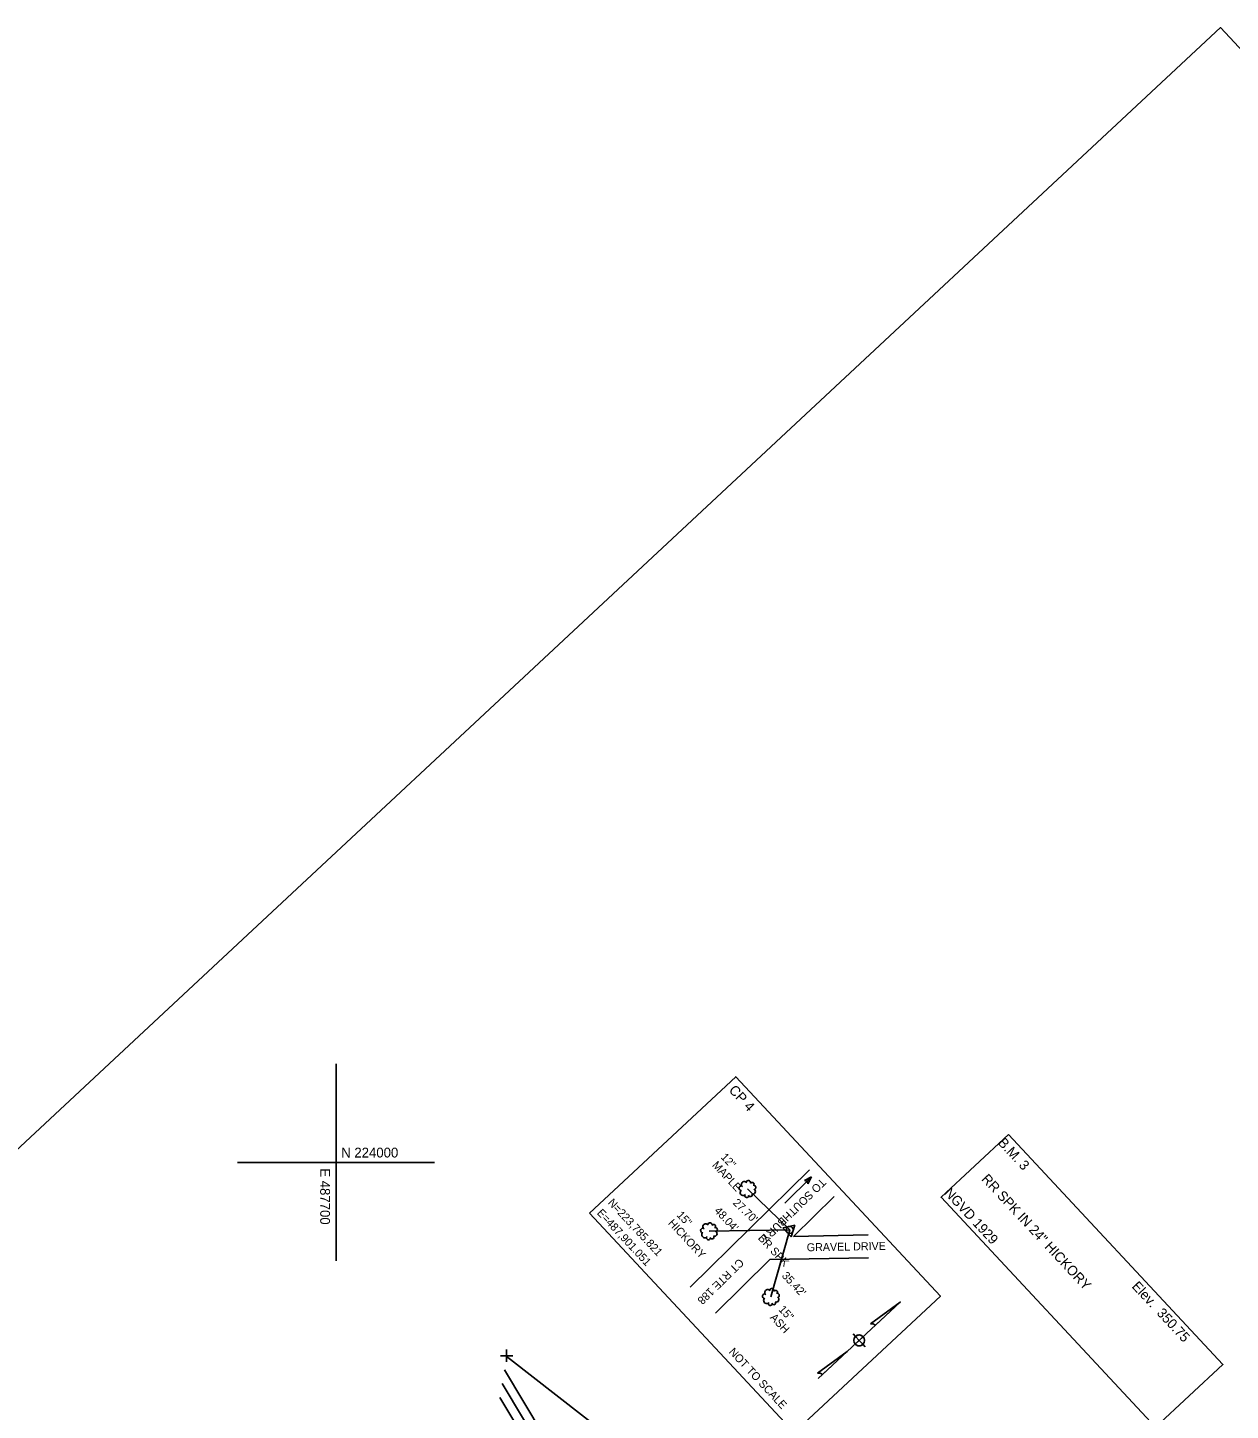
# Model space of a CAD drawing. Extents: x 487096 to 489566, y 221939 to 224454.
# Drawn here: x 487577 to 488058, y 223901 to 224454 of the extents above; entities that cross this region are included whole.
import ezdxf

# ---------------------------------------------------------------- set-up
doc = ezdxf.new("R2010")
doc.units = 0
for name, color, linetype in [('SV_CTRL_BM_INFO_BOX', 7, 'Continuous'), ('SV_CTRL_TIE_BOX', 7, 'Continuous'), ('SV_GRID_GRID', 7, 'Continuous'), ('SV_MAPI_BORDERS', 7, 'Continuous'), ('SV_SURF_INTER_CONTOUR', 7, 'Continuous'), ('SV_SURF_SPOT', 7, 'Continuous')]:
    doc.layers.add(name, color=color, linetype=linetype)

msp = doc.modelspace()

# ---------------------------------------------------------------- linework, layer by layer
at = {"layer": 'SV_CTRL_BM_INFO_BOX'}
msp.add_lwpolyline([(487968.92, 224011.17), (488054.7, 223919.18), (488027.75, 223894.06), (487941.97, 223986.04)], close=True, dxfattribs=at)
at = {"layer": 'SV_CTRL_TIE_BOX'}
for p, q in [((487889.3, 223997.07), (487841.59, 223950.13)), ((487879.48, 223983.69), (487890.17, 223994.22)), ((487890.17, 223994.22), (487887.33, 223992.83)), ((487888.74, 223991.4), (487890.17, 223994.22)), ((487864.56, 223989.39), (487864.56, 223989.39)), ((487899.2, 223986.39), (487882.98, 223970.43)), ((487881.43, 223973), (487849.2, 223972.48)), ((487849.2, 223972.48), (487849.2, 223972.48)), ((487883.53, 223974.95), (487878.69, 223973.83)), ((487878.69, 223973.83), (487882.07, 223970.2)), ((487881.43, 223973), (487881.43, 223973)), ((487882.07, 223970.2), (487883.53, 223974.95)), ((487882.98, 223970.43), (487912.83, 223971)), ((487873.51, 223961.11), (487851.81, 223939.75)), ((487873.51, 223961.11), (487913, 223961.86)), ((487873.93, 223946.17), (487873.93, 223946.17)), ((487892.8, 223913.51), (487925.63, 223944.13)), ((487906.76, 223931.45), (487907.74, 223930.4)), ((487915.69, 223934.86), (487915.69, 223934.86)), ((487915.69, 223934.86), (487915.69, 223934.86)), ((487907.63, 223927.35), (487909.21, 223928.82)), ((487907.74, 223930.4), (487909.21, 223928.82)), ((487909.21, 223928.82), (487910.79, 223930.29)), ((487909.21, 223928.82), (487909.21, 223928.82)), ((487909.21, 223928.82), (487910.69, 223927.24)), ((487910.69, 223927.24), (487911.67, 223926.19)), ((487892.53, 223915.68), (487904.46, 223924.39)), ((487894.52, 223915.12), (487904.46, 223924.39)), ((487904.46, 223924.39), (487894.52, 223915.12))]:
    msp.add_line(p, q, dxfattribs=at)
msp.add_lwpolyline([(487801.33, 223979.69), (487883.17, 223891.93), (487941.68, 223946.48), (487859.84, 224034.25)], close=True, dxfattribs=at)
for points in [[(487864.56, 223989.39), (487881.43, 223973), (487873.93, 223946.17)], [(487913.7, 223935.42), (487925.63, 223944.13), (487915.69, 223934.86), (487915.69, 223934.86)], [(487913.7, 223935.42), (487925.63, 223944.13), (487915.69, 223934.86), (487915.69, 223934.86)], [(487913.7, 223935.42), (487925.63, 223944.13), (487915.69, 223934.86), (487915.69, 223934.86)]]:
    msp.add_lwpolyline(points, dxfattribs=at)
for centre, radius in [((487881.43, 223973), 1.43), ((487909.21, 223928.82), 2.16)]:
    msp.add_circle(centre, radius, dxfattribs=at)
for centre, radius, start, end in [((487863.24, 223991.16), 1.17, 32.3292, 232.9889), ((487864.9, 223991.9), 0.874, 348.9933, 164.459), ((487866.42, 223991.27), 0.75, 336.2911, 145.3579), ((487887.11, 223991.2), 1.64, 6.939, 82.1407), ((487862.08, 223989.69), 0.922, 90.0157, 257.5501), ((487866.68, 223988.4), 1.06, 247.1859, 64.1082), ((487867.02, 223990.03), 0.85, 298.5308, 105.7093), ((487847.87, 223974.26), 1.17, 32.3292, 232.9889), ((487849.53, 223975), 0.874, 348.9933, 164.459), ((487851.06, 223974.37), 0.75, 336.2911, 145.3579), ((487846.72, 223972.79), 0.922, 90.0157, 257.5501), ((487851.32, 223971.5), 1.06, 247.1859, 64.1082), ((487851.65, 223973.13), 0.85, 298.5308, 105.7093), ((487872.6, 223947.95), 1.17, 32.3292, 232.9889), ((487874.26, 223948.69), 0.874, 348.9933, 164.459), ((487875.79, 223948.06), 0.75, 336.2911, 145.3579), ((487876.38, 223946.82), 0.85, 298.5308, 105.7093), ((487871.45, 223946.48), 0.922, 90.0157, 257.5501), ((487876.05, 223945.19), 1.06, 247.1859, 64.1082), ((487909.21, 223928.82), 2.16, 43, 132.985), ((487914.24, 223933.51), 1.99, 43, 105.6885), ((487914.24, 223933.51), 1.99, 43, 105.6885), ((487909.21, 223928.82), 2.18, 223, 313.0149), ((487893.07, 223913.77), 1.99, 43, 105.6885)]:
    msp.add_arc(centre, radius, start, end, dxfattribs=at)
for centre, major_axis, ratio, start_param, end_param in [((487862.76, 223987.89), (-0.699, 0.983), 0.902156, 0, 3.5401), ((487864.29, 223986.79), (-0.529, -0.603), 0.999752, 5.391582, 8.241319), ((487865.67, 223987.07), (0.551, -0.61), 0.901056, 4.216583, 7.444153), ((487847.4, 223970.98), (-0.699, 0.983), 0.902156, 0, 3.5401), ((487848.93, 223969.88), (-0.529, -0.603), 0.999752, 5.391582, 8.241319), ((487850.31, 223970.16), (0.551, -0.61), 0.901056, 4.216583, 7.444153), ((487872.13, 223944.68), (-0.699, 0.983), 0.902156, 0, 3.5401), ((487873.66, 223943.57), (-0.529, -0.603), 0.999752, 5.391582, 8.241319), ((487875.04, 223943.86), (0.551, -0.61), 0.901056, 4.216583, 7.444153)]:
    msp.add_ellipse(centre, major_axis=major_axis, ratio=ratio, start_param=start_param, end_param=end_param, dxfattribs=at)
at = {"layer": 'SV_GRID_GRID'}
for p, q in [((487700, 224000), (487700, 224039.37)), ((487660.63, 224000), (487700, 224000)), ((487700, 224000), (487739.37, 224000)), ((487700, 224000), (487700, 223960.63))]:
    msp.add_line(p, q, dxfattribs=at)
at = {"layer": 'SV_MAPI_BORDERS'}
msp.add_lwpolyline([(488607.95, 221938.76), (487095.64, 223560.51), (488053.67, 224453.88), (489565.97, 222832.14)], close=True, dxfattribs=at)
at = {"layer": 'SV_SURF_INTER_CONTOUR'}
for points in [[(487947.85, 223849.1), (487908.48, 223863.23), (487891.57, 223864.75), (487887.71, 223866.17), (487882.21, 223866.46), (487844.7, 223872.16), (487807.27, 223891.91), (487769.81, 223921.23), (487768.69, 223922.01), (487768.47, 223922.17), (487768.22, 223922.59)], [(487978.37, 223836.41), (487918.82, 223857.78), (487893.24, 223860.08), (487887.4, 223862.23), (487879.08, 223862.67), (487846.53, 223867.61), (487802.76, 223890.71), (487802.25, 223889.59), (487792.04, 223888.75), (487787.06, 223888.11), (487782.82, 223891.17), (487767.31, 223917.05)], [(487766.39, 223911.52), (487783.04, 223883.73)], [(487765.48, 223905.98), (487780.53, 223880.87)]]:
    msp.add_lwpolyline(points, dxfattribs=at)
at = {"layer": 'SV_SURF_SPOT'}
for p, q in [((487765.73, 223922.68), (487770.73, 223922.68)), ((487768.23, 223920.18), (487768.23, 223925.18)), ((487768.23, 223922.68), (487768.23, 223922.68))]:
    msp.add_line(p, q, dxfattribs=at)

# ---------------------------------------------------------------- texts
at = {"layer": 'SV_CTRL_BM_INFO_BOX'}
for s, p in [(' B.M. 3    ', (487963.44, 224008.72)), (' RR SPK IN 24" HICKORY                    ', (487956.89, 223994.21)), (' NGVD 1929', (487941.96, 223988.69)), ('Elev.  350.75  ', (488018.01, 223950.21))]:
    msp.add_text(s, height=3.937, rotation=313, dxfattribs=at).set_placement(p)
at = {"layer": 'SV_CTRL_TIE_BOX'}
for s, height, rotation, p in [('CP 4                           ', 4, 312.965, (487856.81, 224028.69)), ('12"', 3.2, 313, (487853.65, 224001.92)), ('MAPLE', 3.2, 313, (487850.22, 223998.71)), ('TO SOUTHBURY', 3.2, 224.5398, (487894.03, 223993.9)), ('E=487,901.051  ', 3.2, 313, (487804.12, 223979.61)), ('N=223,785.821  ', 3.2, 313, (487808.51, 223983.71)), ("48.04'", 3.2, 313, (487851.06, 223980.46)), ("27.70'", 3.2, 315.8223, (487858.46, 223983.58)), ('HICKORY', 3.2, 313, (487832.58, 223975.53)), ('15"', 3.2, 313, (487836.02, 223978.73)), ('BR SPK', 3.2, 313, (487868.52, 223969.55)), ('GRAVEL DRIVE', 3.2, 1.0864, (487888.28, 223964.43)), ('CT RTE 188', 3.2, 224.5398, (487861.22, 223961.8)), ("35.42'", 3.2, 313, (487878.06, 223954.49)), ('15"', 3.2, 313, (487876.76, 223940.99)), ('ASH', 3.2, 313, (487873.33, 223937.78)), ('NOT TO SCALE', 3.2, 313, (487856.88, 223924.04))]:
    msp.add_text(s, height=height, rotation=rotation, dxfattribs=at).set_placement(p)
at = {"layer": 'SV_GRID_GRID'}
msp.add_text('N 224000', height=3.937, dxfattribs=at).set_placement((487702.05, 224001.96))
msp.add_text('E 487700', height=3.937, rotation=270, dxfattribs=at).set_placement((487693.65, 223997.64))

doc.saveas('drawing.dxf')
